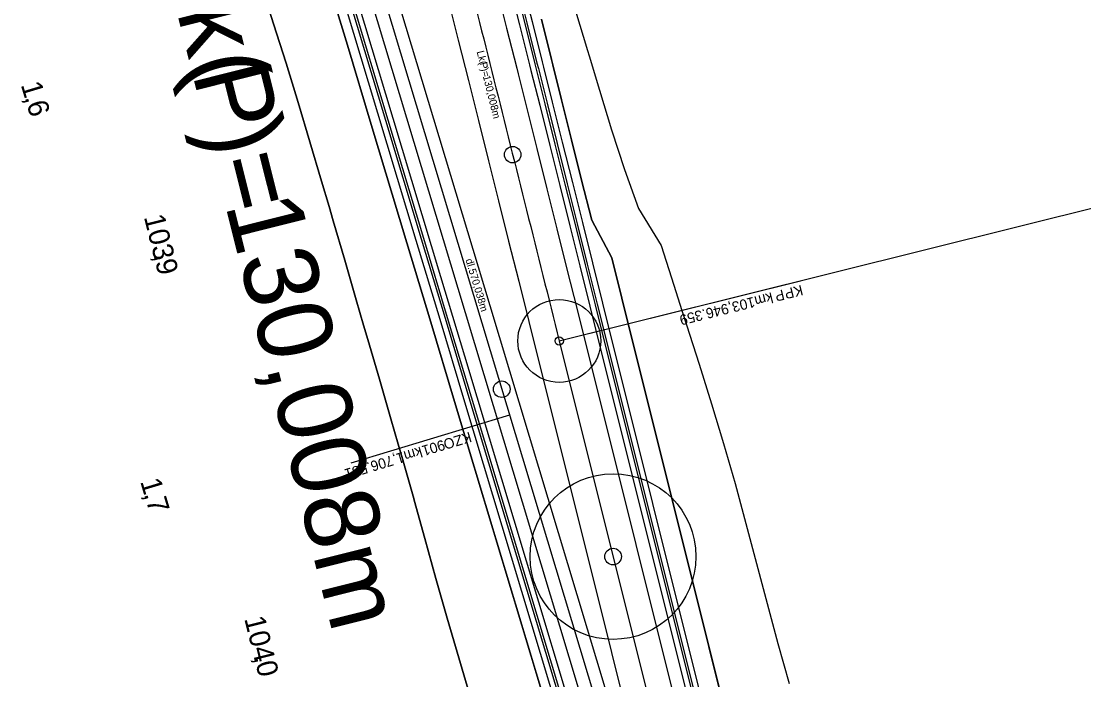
# Model space of a CAD drawing. Extents: x -678487 to -674601, y -1104811 to -1093295.
# Drawn here: x -676211.3 to -675954.9, y -1100621.8 to -1100462.9 of the extents above; entities that cross this region are included whole.
import ezdxf

# ---------------------------------------------------------------- set-up
doc = ezdxf.new("R2010")
doc.units = 0
for name, color, linetype in [('SOxx02xx_Koleje_LN_staničení_zaoblení_Popis', 7, 'Continuous'), ('SOxx02xx_Koleje_param další_Popis', 7, 'Continuous'), ('SOxx02xx_Staničení_Popis', 7, 'Continuous'), ('SOxx02xx_ŽSp_hrana', 7, 'Continuous'), ('SOxx02xx_ŽSp_odvodnění', 7, 'Continuous'), ('SOxx02xx_ŽSp_zářez_hrana', 7, 'Continuous'), ('SOxx02xx_ŽSp_zářez_plocha', 7, 'Continuous'), ('SOxxxxxx_Koleje_hlavní_body_Popis', 7, 'Continuous'), ('SOxxxxxx_Koleje_hlavní_body_Popis10', 7, 'Continuous'), ('SOxxxxxx_Koleje_param další_Popis', 7, 'Continuous'), ('SOxxxxxx_Koleje_param další_Popis10', 7, 'Continuous'), ('SOxxxxxx_Osa_bod_P', 7, 'Continuous'), ('SOxxxxxx_Staničení_Popis', 7, 'Continuous'), ('SOxxxxxx_Staničení_Popis10', 7, 'Continuous'), ('SOxxxxxx_ŽSp_hrana', 7, 'Continuous'), ('SOxxxxxx_ŽSp_odvodnění', 7, 'Continuous'), ('SOxxxxxx_ŽSp_zářez_hrana', 7, 'Continuous'), ('SOxxxxxx_ŽSp_zářez_plocha', 7, 'Continuous')]:
    doc.layers.add(name, color=color, linetype=linetype)

msp = doc.modelspace()

# ---------------------------------------------------------------- linework, layer by layer
at = {"layer": 'SOxx02xx_Koleje_LN_staničení_zaoblení_Popis'}
msp.add_line((-676093.49, -1100557.99), (-676131.79, -1100569.52), dxfattribs=at)
at = {"layer": 'SOxx02xx_Staničení_Popis'}
msp.add_circle((-676095.39, -1100551.69), 2, dxfattribs=at)
at = {"layer": 'SOxx02xx_ŽSp_hrana'}
for points in [[(-676048.99, -1100695.12), (-676098.21, -1100531.55), (-676121.24, -1100455), (-676132.31, -1100418.23), (-676144.27, -1100378.48), (-676155.78, -1100340.22), (-676170.18, -1100292.38), (-676181.16, -1100255.89), (-676184.59, -1100244.51), (-676187.47, -1100234.94), (-676189.32, -1100228.81), (-676190.37, -1100225.36), (-676193.28, -1100215.79), (-676196.21, -1100206.23), (-676196.84, -1100204.21)], [(-676202.69, -1100206.25), (-676202.07, -1100208.27), (-676199.14, -1100217.82), (-676196.23, -1100227.38), (-676195.19, -1100230.83), (-676193.34, -1100236.94), (-676190.46, -1100246.5), (-676187.04, -1100257.87), (-676176.07, -1100294.31), (-676161.69, -1100342.09), (-676150.19, -1100380.31), (-676138.25, -1100420), (-676127.2, -1100456.73), (-676104.19, -1100533.2), (-676017.42, -1100821.54)]]:
    msp.add_lwpolyline(points, dxfattribs=at)
at = {"layer": 'SOxx02xx_ŽSp_odvodnění'}
for p, q in [((-676131.52, -1100457.99), (-676122.9, -1100486.63)), ((-676122.9, -1100486.63), (-676114.28, -1100515.27)), ((-676114.28, -1100515.27), (-676108.53, -1100534.39)), ((-676108.53, -1100534.39), (-676102.77, -1100553.54)), ((-676102.77, -1100553.54), (-676021.77, -1100822.71))]:
    msp.add_line(p, q, dxfattribs=at)
msp.add_lwpolyline([(-676207.46, -1100207.91), (-676206.84, -1100209.93), (-676203.91, -1100219.47), (-676201.01, -1100229.02), (-676199.97, -1100232.46), (-676198.12, -1100238.57), (-676195.24, -1100248.12), (-676191.82, -1100259.48), (-676183.7, -1100286.49), (-676175.13, -1100314.98), (-676166.51, -1100343.62), (-676157.89, -1100372.25), (-676149.28, -1100400.88), (-676140.66, -1100429.51), (-676132.05, -1100458.14), (-676123.43, -1100486.78), (-676114.81, -1100515.42), (-676109.06, -1100534.54), (-676103.3, -1100553.68), (-676022.3, -1100822.85)], dxfattribs=at)
at = {"layer": 'SOxx02xx_ŽSp_zářez_hrana'}
for p, q in [((-676153.45, -1100454.03), (-676150.47, -1100463.5)), ((-676150.47, -1100463.5), (-676147.42, -1100472.95)), ((-676147.42, -1100472.95), (-676145.07, -1100480.65)), ((-676145.07, -1100480.65), (-676144.53, -1100482.45)), ((-676144.53, -1100482.45), (-676141.67, -1100491.96)), ((-676141.67, -1100491.96), (-676138.91, -1100501.5)), ((-676138.91, -1100501.5), (-676137.08, -1100507.57)), ((-676137.08, -1100507.57), (-676136.04, -1100511.01)), ((-676136.04, -1100511.01), (-676133.25, -1100520.55)), ((-676133.25, -1100520.55), (-676130.5, -1100530.11)), ((-676130.5, -1100530.11), (-676128.72, -1100536.22)), ((-676128.72, -1100536.22), (-676127.71, -1100539.68)), ((-676127.71, -1100539.68), (-676124.92, -1100549.25)), ((-676124.92, -1100549.25), (-676122.14, -1100558.85)), ((-676122.14, -1100558.85), (-676120.37, -1100564.98)), ((-676120.37, -1100564.98), (-676119.37, -1100568.46)), ((-676119.37, -1100568.46), (-676116.61, -1100578.07)), ((-676116.61, -1100578.07), (-676116.5, -1100578.46)), ((-676116.5, -1100578.46), (-676113.97, -1100587.71)), ((-676113.97, -1100587.71), (-676111.33, -1100597.36)), ((-676111.33, -1100597.36), (-676108.54, -1100606.96)), ((-676108.54, -1100606.96), (-676105.75, -1100616.57)), ((-676105.75, -1100616.57), (-676102.9, -1100626.15))]:
    msp.add_line(p, q, dxfattribs=at)
for points in [[(-676205.73, -1100207.31), (-676205.11, -1100209.33), (-676202.18, -1100218.87), (-676199.28, -1100228.42), (-676198.23, -1100231.87), (-676196.39, -1100237.98), (-676193.51, -1100247.54), (-676190.09, -1100258.89), (-676181.96, -1100285.91), (-676173.38, -1100314.42), (-676164.76, -1100343.06), (-676156.14, -1100371.71), (-676147.53, -1100400.35), (-676138.91, -1100428.99), (-676130.29, -1100457.63), (-676121.67, -1100486.28), (-676110.17, -1100524.49), (-676104.41, -1100543.62), (-676020.53, -1100822.38)], [(-676025.78, -1100823.79), (-676106.77, -1100554.63), (-676112.53, -1100535.5), (-676118.28, -1100516.38), (-676126.89, -1100487.76), (-676132.63, -1100468.68), (-676138.37, -1100449.61), (-676144.11, -1100430.54), (-676149.85, -1100411.46), (-676154.65, -1100395.52), (-676161.33, -1100373.32), (-676169.94, -1100344.7), (-676178.55, -1100316.09), (-676184.29, -1100297), (-676190.03, -1100277.92), (-676195.24, -1100260.63), (-676198.65, -1100249.28), (-676201.53, -1100239.73), (-676203.37, -1100233.63), (-676204.41, -1100230.19), (-676207.32, -1100220.65), (-676210.24, -1100211.11), (-676210.86, -1100209.1)], [(-676023.53, -1100823.19), (-676104.53, -1100554.02), (-676110.29, -1100534.88), (-676116.04, -1100515.76), (-676127.53, -1100477.58), (-676136.15, -1100448.96), (-676144.31, -1100421.82), (-676150.5, -1100401.25), (-676159.12, -1100372.63), (-676167.73, -1100344), (-676176.34, -1100315.37), (-676184.91, -1100286.89), (-676193.04, -1100259.89), (-676196.45, -1100248.53), (-676199.33, -1100238.98), (-676201.18, -1100232.88), (-676202.22, -1100229.43), (-676205.12, -1100219.89), (-676208.05, -1100210.35), (-676208.67, -1100208.34)]]:
    msp.add_lwpolyline(points, dxfattribs=at)
at = {"layer": 'SOxx02xx_ŽSp_zářez_plocha'}
for points in [[(-676210.86, -1100209.1), (-676210.24, -1100211.11), (-676207.32, -1100220.65), (-676204.41, -1100230.19), (-676203.37, -1100233.63), (-676201.53, -1100239.73), (-676198.65, -1100249.28), (-676195.24, -1100260.63), (-676190.03, -1100277.92), (-676184.29, -1100297), (-676178.55, -1100316.09), (-676169.94, -1100344.7), (-676161.33, -1100373.32), (-676154.65, -1100395.52), (-676149.85, -1100411.46), (-676144.11, -1100430.54), (-676138.37, -1100449.61), (-676132.63, -1100468.68), (-676126.89, -1100487.76), (-676118.28, -1100516.38), (-676112.53, -1100535.5), (-676106.77, -1100554.63), (-676042.65, -1100767.7)], [(-676102.9, -1100626.15), (-676105.75, -1100616.57), (-676108.54, -1100606.96), (-676111.33, -1100597.36), (-676113.97, -1100587.71), (-676116.5, -1100578.46), (-676116.61, -1100578.07), (-676119.37, -1100568.46), (-676120.37, -1100564.98), (-676122.14, -1100558.85), (-676124.92, -1100549.25), (-676127.71, -1100539.68), (-676128.72, -1100536.22), (-676130.5, -1100530.11), (-676133.25, -1100520.55), (-676136.04, -1100511.01), (-676137.08, -1100507.57), (-676138.91, -1100501.5), (-676141.67, -1100491.96), (-676144.53, -1100482.45), (-676145.07, -1100480.65), (-676147.42, -1100472.95), (-676150.47, -1100463.5), (-676153.45, -1100454.03)]]:
    msp.add_lwpolyline(points, dxfattribs=at)
at = {"layer": 'SOxxxxxx_Koleje_hlavní_body_Popis'}
for q in [(-676023.31, -1100525.51), (-676081.52, -1100540.04)]:
    msp.add_line((-676081.52, -1100540.04), q, dxfattribs=at)
msp.add_circle((-676081.52, -1100540.04), 1, dxfattribs=at)
at = {"layer": 'SOxxxxxx_Koleje_hlavní_body_Popis10'}
for q in [(-675499.4, -1100394.68), (-676081.52, -1100540.04)]:
    msp.add_line((-676081.52, -1100540.04), q, dxfattribs=at)
msp.add_circle((-676081.52, -1100540.04), 10, dxfattribs=at)
at = {"layer": 'SOxxxxxx_Osa_bod_P'}
for p, q in [((-676185.24, -1100253.08), (-676020.99, -1100798.94)), ((-676081.52, -1100540.04), (-675711.08, -1102023.47))]:
    msp.add_line(p, q, dxfattribs=at)
msp.add_open_spline([(-676113.17, -1100413.95), (-676110.51, -1100424.45), (-676105.2, -1100445.46), (-676097.28, -1100476.98), (-676089.39, -1100508.51), (-676084.14, -1100529.53), (-676081.52, -1100540.04)], degree=3, dxfattribs=at)
at = {"layer": 'SOxxxxxx_Staničení_Popis'}
for p, q in [((-676092.76, -1100495.07), (-676092.76, -1100495.07)), ((-676095.39, -1100551.69), (-676095.39, -1100551.69)), ((-676068.52, -1100592.09), (-676068.52, -1100592.09))]:
    msp.add_line(p, q, dxfattribs=at)
for centre in [(-676092.76, -1100495.07), (-676095.39, -1100551.69), (-676068.52, -1100592.09)]:
    msp.add_circle(centre, 2, dxfattribs=at)
at = {"layer": 'SOxxxxxx_Staničení_Popis10'}
msp.add_line((-676068.52, -1100592.09), (-676068.52, -1100592.09), dxfattribs=at)
msp.add_circle((-676068.52, -1100592.09), 20, dxfattribs=at)
at = {"layer": 'SOxxxxxx_ŽSp_hrana'}
for points in [[(-676121.28, -1100357.85), (-676120.3, -1100361.68), (-676118.8, -1100367.54), (-676116.32, -1100377.23), (-676113.84, -1100386.92), (-676111.37, -1100396.62), (-676108.91, -1100406.31), (-676107.34, -1100412.47), (-676106.45, -1100416.01), (-676103.99, -1100425.71), (-676101.54, -1100435.4), (-676099.1, -1100445.1), (-676096.66, -1100454.8), (-676094.22, -1100464.5), (-676091.79, -1100474.21), (-676091.46, -1100475.52), (-676089.36, -1100483.91), (-676086.93, -1100493.61), (-676084.5, -1100503.31), (-676082.08, -1100513.01), (-676079.65, -1100522.72), (-676077.23, -1100532.42), (-675977.9, -1100930.2)], [(-676108.32, -1100457.73), (-676105.88, -1100467.43), (-676103.45, -1100477.13), (-676103.12, -1100478.44), (-676101.02, -1100486.83), (-676098.59, -1100496.53), (-676096.16, -1100506.23), (-676093.74, -1100515.93), (-676091.31, -1100525.63), (-676088.89, -1100535.33), (-676048.99, -1100695.12)]]:
    msp.add_lwpolyline(points, dxfattribs=at)
at = {"layer": 'SOxxxxxx_ŽSp_odvodnění'}
for p, q in [((-676092.29, -1100453.71), (-676089.86, -1100463.41)), ((-676091.76, -1100453.57), (-676089.32, -1100463.28)), ((-676089.86, -1100463.41), (-676087.42, -1100473.11)), ((-676089.32, -1100463.28), (-676086.89, -1100472.98)), ((-676087.42, -1100473.11), (-676087.09, -1100474.43)), ((-676087.09, -1100474.43), (-676084.99, -1100482.81)), ((-676086.89, -1100472.98), (-676086.56, -1100474.29)), ((-676086.56, -1100474.29), (-676084.46, -1100482.68)), ((-676084.99, -1100482.81), (-676082.56, -1100492.52)), ((-676084.46, -1100482.68), (-676082.03, -1100492.38)), ((-676082.56, -1100492.52), (-676080.14, -1100502.22)), ((-676082.03, -1100492.38), (-676079.6, -1100502.09)), ((-676080.14, -1100502.22), (-676077.71, -1100511.92)), ((-676079.6, -1100502.09), (-676077.18, -1100511.79)), ((-676077.71, -1100511.92), (-676075.29, -1100521.63)), ((-676077.18, -1100511.79), (-676074.75, -1100521.49)), ((-676075.29, -1100521.63), (-676072.86, -1100531.33)), ((-676074.75, -1100521.49), (-676072.33, -1100531.2)), ((-676072.33, -1100531.2), (-675993.59, -1100846.51)), ((-676072.86, -1100531.33), (-675994.12, -1100846.65))]:
    msp.add_line(p, q, dxfattribs=at)
at = {"layer": 'SOxxxxxx_ŽSp_zářez_hrana'}
for p, q in [((-676093.54, -1100454.02), (-676091.1, -1100463.72)), ((-676090.52, -1100453.26), (-676088.08, -1100462.96)), ((-676077.62, -1100460.34), (-676074.68, -1100469.92)), ((-676091.1, -1100463.72), (-676088.66, -1100473.42)), ((-676088.08, -1100462.96), (-676085.65, -1100472.67)), ((-676085.83, -1100462.4), (-676083.4, -1100472.1)), ((-676083.4, -1100472.1), (-676083.07, -1100473.42)), ((-676074.68, -1100469.92), (-676074.28, -1100471.21)), ((-676074.28, -1100471.21), (-676071.82, -1100479.51)), ((-676088.66, -1100473.42), (-676088.34, -1100474.74)), ((-676088.34, -1100474.74), (-676086.23, -1100483.13)), ((-676085.65, -1100472.67), (-676085.32, -1100473.98)), ((-676085.32, -1100473.98), (-676083.22, -1100482.37)), ((-676083.07, -1100473.42), (-676080.97, -1100481.81)), ((-676071.82, -1100479.51), (-676068.87, -1100489.09)), ((-676083.22, -1100482.37), (-676080.79, -1100492.07)), ((-676080.97, -1100481.81), (-676078.54, -1100491.51)), ((-676086.23, -1100483.13), (-676083.8, -1100492.83)), ((-676068.87, -1100489.09), (-676065.75, -1100498.62)), ((-676083.8, -1100492.83), (-676081.38, -1100502.53)), ((-676080.79, -1100492.07), (-676078.36, -1100501.78)), ((-676078.54, -1100491.51), (-676076.11, -1100501.21)), ((-676065.75, -1100498.62), (-676062.39, -1100508.1)), ((-676081.38, -1100502.53), (-676078.95, -1100512.23)), ((-676078.36, -1100501.78), (-676075.94, -1100511.48)), ((-676076.11, -1100501.21), (-676073.68, -1100510.92)), ((-676062.39, -1100508.1), (-676056.92, -1100517.04)), ((-676078.95, -1100512.23), (-676076.53, -1100521.94)), ((-676075.94, -1100511.48), (-676073.51, -1100521.18)), ((-676073.68, -1100510.92), (-676068.84, -1100520.01)), ((-676056.92, -1100517.04), (-676053.88, -1100526.59)), ((-676068.84, -1100520.01), (-676066.41, -1100529.72)), ((-676076.53, -1100521.94), (-676074.11, -1100531.64)), ((-676073.51, -1100521.18), (-676071.09, -1100530.89)), ((-676053.88, -1100526.59), (-676051.95, -1100532.66)), ((-676071.09, -1100530.89), (-675992.35, -1100846.2)), ((-676066.41, -1100529.72), (-676003.42, -1100781.97)), ((-676074.11, -1100531.64), (-675995.37, -1100846.96)), ((-676051.95, -1100532.66), (-676050.83, -1100536.13)), ((-676050.83, -1100536.13), (-676047.79, -1100545.68)), ((-676047.79, -1100545.68), (-676044.79, -1100555.24)), ((-676044.79, -1100555.24), (-676041.89, -1100564.82)), ((-676041.89, -1100564.82), (-676039.08, -1100574.43)), ((-676039.08, -1100574.43), (-676036.5, -1100584.09)), ((-676036.5, -1100584.09), (-676033.91, -1100593.75)), ((-676033.91, -1100593.75), (-676031.36, -1100603.42)), ((-676031.36, -1100603.42), (-676028.78, -1100613.08)), ((-676028.78, -1100613.08), (-676026.07, -1100622.71))]:
    msp.add_line(p, q, dxfattribs=at)
at = {"layer": 'SOxxxxxx_ŽSp_zářez_plocha'}
for points in [[(-676077.62, -1100460.34), (-676074.68, -1100469.92), (-676074.28, -1100471.21), (-676071.82, -1100479.51), (-676068.87, -1100489.09), (-676065.75, -1100498.62), (-676062.39, -1100508.1), (-676056.92, -1100517.04), (-676053.88, -1100526.59), (-676051.95, -1100532.66), (-676050.83, -1100536.13), (-676047.79, -1100545.68), (-676044.79, -1100555.24), (-676041.89, -1100564.82), (-676039.08, -1100574.43), (-676036.5, -1100584.09), (-676033.91, -1100593.75), (-676031.36, -1100603.42), (-676028.78, -1100613.08), (-676026.07, -1100622.71)], [(-676003.42, -1100781.97), (-676066.41, -1100529.72), (-676068.84, -1100520.01), (-676073.68, -1100510.92), (-676076.11, -1100501.21), (-676078.54, -1100491.51), (-676080.97, -1100481.81), (-676083.07, -1100473.42), (-676083.4, -1100472.1), (-676085.83, -1100462.4)]]:
    msp.add_lwpolyline(points, dxfattribs=at)

# ---------------------------------------------------------------- texts
at = {"layer": 'SOxx02xx_Koleje_LN_staničení_zaoblení_Popis'}
for s, p in [('KZO', (-676103.14, -1100561.94)), ('901', (-676109.54, -1100563.86)), ('1,706.581', (-676119.3, -1100566.8)), (' km ', (-676114.12, -1100565.24))]:
    msp.add_text(s, height=2.5, rotation=196.7473, dxfattribs=at).set_placement(p)
at = {"layer": 'SOxx02xx_Koleje_param další_Popis'}
msp.add_text('dl.570,038m', height=1.8, rotation=286.7473, dxfattribs=at).set_placement((-676104.16, -1100520.46))
at = {"layer": 'SOxx02xx_Staničení_Popis'}
for s, p in [('1', (-676211.49, -1100478.18)), (',', (-676210.57, -1100481.23)), ('6', (-676210.12, -1100482.76)), ('1', (-676182.68, -1100573.94)), (',', (-676181.76, -1100576.99)), ('7', (-676181.3, -1100578.52))]:
    msp.add_text(s, height=5, rotation=286.7473, dxfattribs=at).set_placement(p)
at = {"layer": 'SOxxxxxx_Koleje_hlavní_body_Popis'}
for s, p in [(' km ', (-676029.4, -1100528.06)), ('P', (-676027.54, -1100527.6)), ('KP', (-676023.07, -1100526.48)), ('103,946.359', (-676034.65, -1100529.37))]:
    msp.add_text(s, height=2.5, rotation=194.0209, dxfattribs=at).set_placement(p)
at = {"layer": 'SOxxxxxx_Koleje_param další_Popis'}
for s, p in [('Lk(', (-676101.46, -1100470.21)), (')=', (-676100.43, -1100474.32)), ('P', (-676100.76, -1100472.99)), ('130,008m', (-676099.97, -1100476.15))]:
    msp.add_text(s, height=1.8, rotation=284.0727, dxfattribs=at).set_placement(p)
at = {"layer": 'SOxxxxxx_Koleje_param další_Popis10'}
for s, p in [('Lk(', (-676177.08, -1100447.62)), ('P', (-676170.11, -1100475.4)), (')=', (-676166.77, -1100488.74)), ('130,008m', (-676162.17, -1100507.09))]:
    msp.add_text(s, height=18, rotation=284.0727, dxfattribs=at).set_placement(p)
at = {"layer": 'SOxxxxxx_Staničení_Popis'}
for s, rotation, p in [('1', 286.7473, (-676211.49, -1100478.18)), (',', 286.7473, (-676210.57, -1100481.23)), ('6', 286.7473, (-676210.12, -1100482.76)), ('103', 284.0473, (-676181.78, -1100510.09)), (',', 284.0473, (-676179.46, -1100519.36)), ('9', 284.0473, (-676179.07, -1100520.9)), ('1', 286.7473, (-676182.68, -1100573.94)), (',', 286.7473, (-676181.76, -1100576.99)), ('7', 286.7473, (-676181.3, -1100578.52)), ('104', 284.0209, (-676157.55, -1100607.07)), (',', 284.0209, (-676155.23, -1100616.35)), ('0', 284.0209, (-676154.84, -1100617.89))]:
    msp.add_text(s, height=5, rotation=rotation, dxfattribs=at).set_placement(p)

doc.saveas('drawing.dxf')
